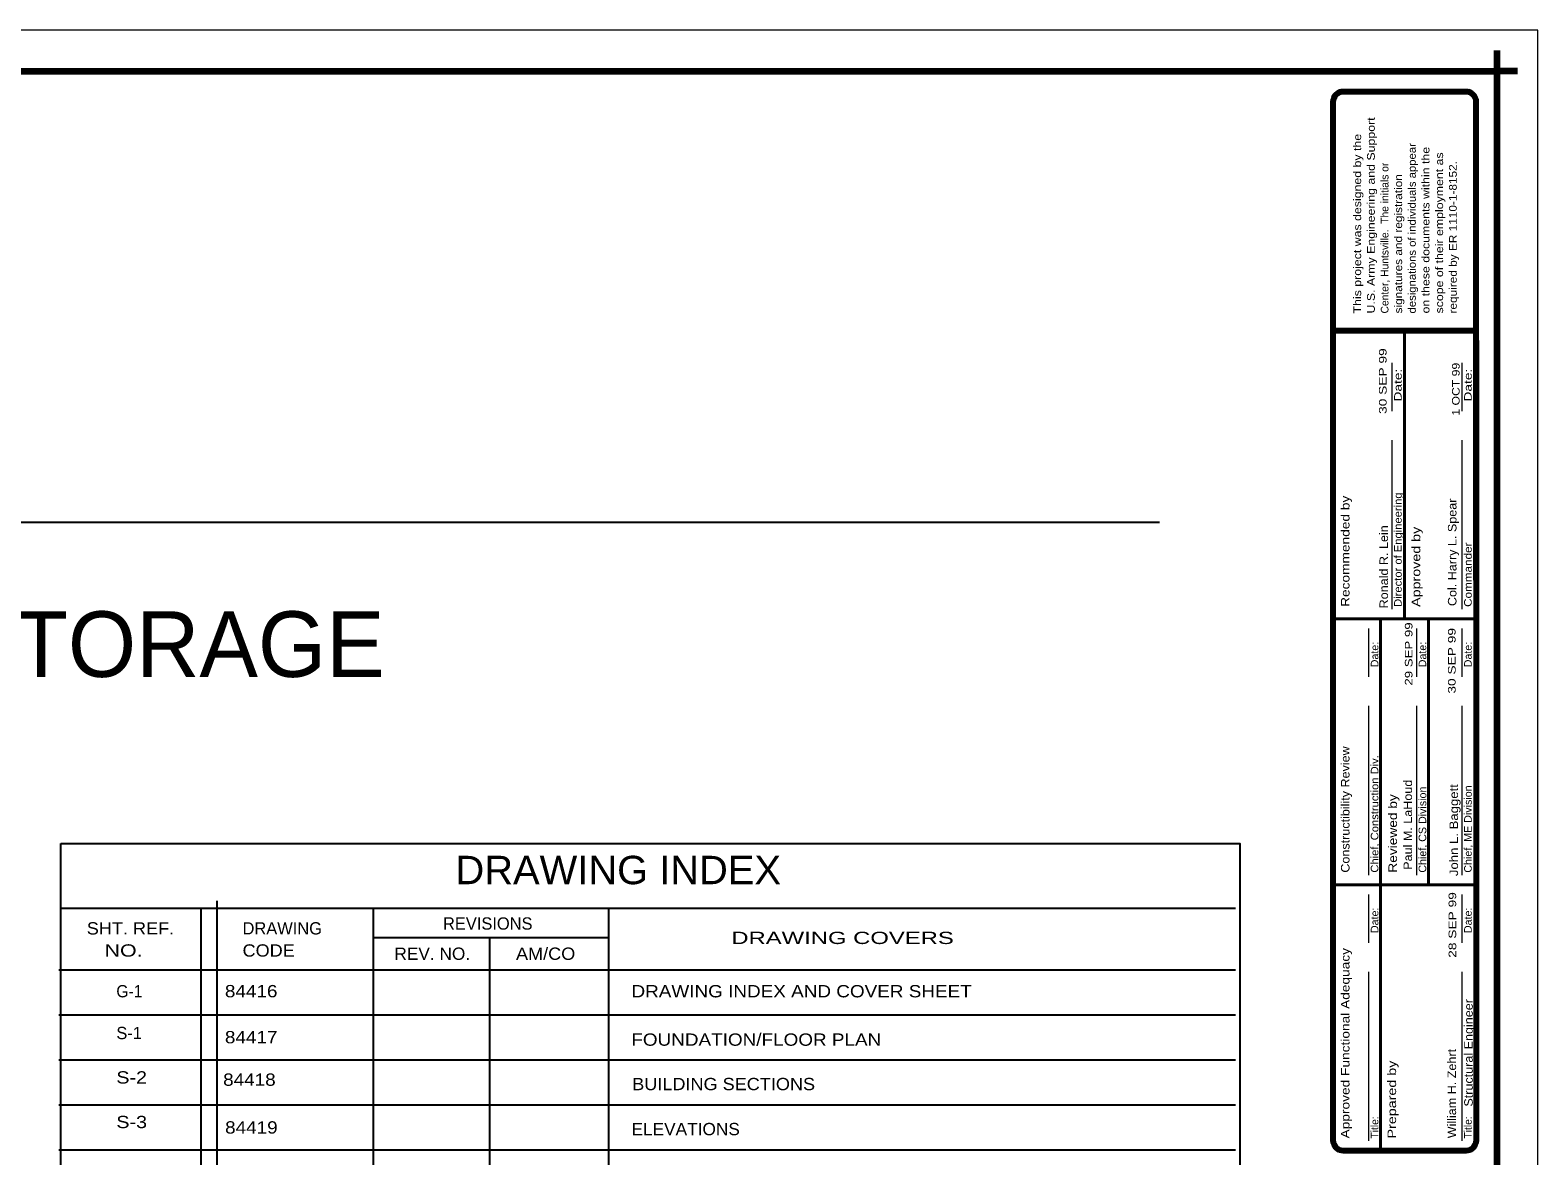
# Model space of a CAD drawing. Extents: x -153.1 to -120, y 360.9 to 384.2.
# Drawn here: x -137.36 to -119.98, y 371.27 to 384.24 of the extents above; entities that cross this region are included whole.
import ezdxf

# ---------------------------------------------------------------- set-up
doc = ezdxf.new("R2010")
doc.units = 0
doc.header["$LTSCALE"] = 0.039
for name, color, linetype, lineweight in [('1', 7, 'Continuous', 80), ('2', 7, 'Continuous', 53), ('3', 7, 'Continuous', 80), ('63', 7, 'Continuous', 25), ('8', 7, 'Continuous', 25)]:
    doc.layers.add(name, color=color, linetype=linetype, lineweight=lineweight)
doc.layers.add('7', color=7, linetype='Continuous')

msp = doc.modelspace()

# ---------------------------------------------------------------- linework, layer by layer
at = {"layer": '1', "lineweight": 90}
for p in [(-120.44775, 384.00407), (-120.44775, 384.00407), (-120.21152, 383.76784), (-120.21152, 383.76784)]:
    msp.add_line(p, (-120.44775, 383.76784), dxfattribs=at)
at = {"layer": '1'}
for p, q in [((-120.80306, 383.53003), (-122.22037, 383.53003)), ((-120.80306, 383.53003), (-122.22037, 383.53003)), ((-122.33848, 383.41193), (-122.33848, 377.90222)), ((-122.33848, 383.41193), (-122.33848, 377.90222)), ((-120.68496, 377.90222), (-120.68496, 383.41193)), ((-120.68496, 377.90222), (-120.68496, 383.41193)), ((-120.68496, 380.7762), (-122.33848, 380.7762)), ((-120.68496, 380.7762), (-122.33848, 380.7762)), ((-122.3375, 380.66461), (-122.3375, 371.44557)), ((-122.3375, 380.66461), (-122.3375, 371.44557)), ((-120.68396, 371.44557), (-120.68396, 380.66461)), ((-120.68396, 371.44557), (-120.68396, 380.66461)), ((-122.21937, 371.32747), (-120.80208, 371.32747)), ((-122.21937, 371.32747), (-120.80208, 371.32747))]:
    msp.add_line(p, q, dxfattribs=at)
at = {"layer": '1', "lineweight": 13}
for p, q in [((-121.65856, 380.40559), (-121.65856, 379.84864)), ((-121.65856, 380.40559), (-121.65856, 379.84864)), ((-120.85104, 380.40559), (-120.85104, 379.84864)), ((-120.85104, 380.40559), (-120.85104, 379.84864)), ((-121.65856, 379.51449), (-121.65856, 377.5652)), ((-121.65856, 379.51449), (-121.65856, 377.5652)), ((-120.85104, 379.51449), (-120.85104, 377.5652)), ((-120.85104, 379.51449), (-120.85104, 377.5652)), ((-121.92727, 377.34243), (-121.92727, 376.78551)), ((-121.92727, 377.34243), (-121.92727, 376.78551)), ((-121.37519, 377.34243), (-121.37519, 376.78551)), ((-121.37519, 377.34243), (-121.37519, 376.78551)), ((-120.85104, 377.34243), (-120.85104, 376.78551)), ((-120.85104, 377.34243), (-120.85104, 376.78551)), ((-121.92727, 376.4513), (-121.92727, 374.50205)), ((-121.92727, 376.4513), (-121.92727, 374.50205)), ((-121.37519, 376.4513), (-121.37519, 374.50205)), ((-121.37519, 376.4513), (-121.37519, 374.50205)), ((-120.85104, 376.4513), (-120.85104, 374.50205)), ((-120.85104, 376.4513), (-120.85104, 374.50205)), ((-121.92727, 374.27924), (-121.92727, 373.72232)), ((-121.92727, 374.27924), (-121.92727, 373.72232)), ((-120.85104, 374.27924), (-120.85104, 373.72232)), ((-120.85104, 374.27924), (-120.85104, 373.72232)), ((-121.92727, 373.38814), (-121.92727, 371.43889)), ((-121.92727, 373.38814), (-121.92727, 371.43889)), ((-120.85104, 373.38814), (-120.85104, 371.43889)), ((-120.85104, 373.38814), (-120.85104, 371.43889))]:
    msp.add_line(p, q, dxfattribs=at)
at = {"layer": '1', "lineweight": 25}
for p in [(-124.33602, 378.5668), (-126.54058, 378.5668)]:
    msp.add_line(p, (-149.54265, 378.5668), dxfattribs=at)
at = {"layer": '1', "lineweight": 13}
msp.add_lwpolyline([(-153.08523, 360.85466), (-119.97531, 360.85466), (-119.97531, 384.24028), (-153.08523, 384.24028)], close=True, dxfattribs=at)
msp.add_lwpolyline([(-153.08523, 360.85466), (-119.97531, 360.85466), (-119.97531, 384.24028), (-153.08523, 384.24028)], close=True, dxfattribs=at)
msp.add_lwpolyline([(-153.08523, 360.85466), (-119.97531, 360.85466), (-119.97531, 384.24028), (-153.08523, 384.24028)], close=True, dxfattribs=at)
at = {"layer": '1', "lineweight": 90}
msp.add_lwpolyline([(-152.02225, 383.76784), (-120.44775, 383.76784), (-120.44775, 361.32709)], dxfattribs=at)
msp.add_lwpolyline([(-152.02225, 383.76784), (-120.44775, 383.76784), (-120.44775, 361.32709)], dxfattribs=at)
msp.add_lwpolyline([(-152.02225, 383.76784), (-120.44775, 383.76784), (-120.44775, 361.32709)], dxfattribs=at)
at = {"layer": '1'}
for centre, start, end in [((-122.21937, 371.44558), 180, 270), ((-122.21937, 371.44558), 180, 270), ((-120.80206, 371.44558), 270, 0), ((-120.80206, 371.44558), 270, 0)]:
    msp.add_arc(centre, 0.11811, start, end, dxfattribs=at)
at = {"layer": '2', "lineweight": 40}
for p, q in [((-121.51073, 380.7762), (-121.51073, 377.4538)), ((-121.51073, 380.7762), (-121.51073, 377.4538)), ((-120.68396, 377.4538), (-122.3375, 377.4538)), ((-120.68396, 377.4538), (-122.3375, 377.4538)), ((-121.788, 377.4538), (-121.788, 371.32747)), ((-121.788, 377.4538), (-121.788, 371.32747)), ((-121.236, 377.4538), (-121.236, 374.39064)), ((-121.236, 377.4538), (-121.236, 374.39064)), ((-120.68396, 374.39064), (-122.3375, 374.39064)), ((-120.68396, 374.39064), (-122.3375, 374.39064))]:
    msp.add_line(p, q, dxfattribs=at)
at = {"layer": '3'}
for centre, start, end in [((-122.22037, 383.41191), 90, 180), ((-122.22037, 383.41191), 90, 180), ((-120.80306, 383.41191), 0, 90), ((-120.80306, 383.41191), 0, 90)]:
    msp.add_arc(centre, 0.11811, start, end, dxfattribs=at)
at = {"layer": '63'}
msp.add_lwpolyline([(-137.00331, 374.8668), (-123.41131, 374.8668), (-123.41131, 361.87971), (-137.00331, 361.87971)], close=True, dxfattribs=at)
at = {"layer": '8'}
for p, q in [((-137.01536, 374.12059), (-123.46037, 374.12059)), ((-135.38806, 374.12059), (-135.38806, 361.89876)), ((-135.20612, 374.20461), (-135.20612, 361.90815)), ((-133.40354, 374.12059), (-133.40354, 361.91753)), ((-130.68806, 374.12059), (-130.68806, 361.90815)), ((-133.40354, 373.78197), (-130.68806, 373.78197)), ((-132.06006, 373.78197), (-132.06006, 361.89876)), ((-137.02615, 373.40903), (-123.46037, 373.40903)), ((-137.02615, 372.89101), (-123.46037, 372.89101)), ((-137.02615, 372.37299), (-123.46037, 372.37299)), ((-137.02615, 371.85497), (-123.46037, 371.85497)), ((-137.02615, 371.33697), (-123.46037, 371.33697))]:
    msp.add_line(p, q, dxfattribs=at)

# ---------------------------------------------------------------- texts
at = {"layer": '1'}
for s, width, p in [('U.S. Army Engineering and Support ', 1.2, (-121.85496, 380.97505)), ('U.S. Army Engineering and Support ', 1.2, (-121.85496, 380.97505)), ('This project was designed by the ', 1.2, (-122.01244, 380.97501)), ('This project was designed by the ', 1.2, (-122.01244, 380.97501)), ('designations of individuals appear', 1.1, (-121.38254, 380.97505)), ('designations of individuals appear', 1.1, (-121.38254, 380.97505)), ('on these documents within the ', 1.2, (-121.22504, 380.97505)), ('on these documents within the ', 1.2, (-121.22504, 380.97505)), ('scope of their employment as ', 1.2, (-121.06756, 380.97505)), ('scope of their employment as ', 1.2, (-121.06756, 380.97505)), ('required by ER 1110-1-8152.', 1.15, (-120.9101, 380.97505)), ('required by ER 1110-1-8152.', 1.15, (-120.9101, 380.97505)), ('signatures and registration ', 1.15, (-121.54, 380.97505)), ('signatures and registration ', 1.15, (-121.54, 380.97505))]:
    msp.add_text(s, height=0.08858, rotation=90, dxfattribs=dict(at, width=width)).set_placement(p)
msp.add_text('Center, Huntsville.  The initials or ', height=0.08858, rotation=90, dxfattribs=at).set_placement((-121.69748, 380.97505))
msp.add_text('Center, Huntsville.  The initials or ', height=0.08858, rotation=90, dxfattribs=at).set_placement((-121.69748, 380.97505))
msp.add_text('AIR FORCE MODULAR STORAGE', height=0.7559, dxfattribs=at).set_placement((-149.33323, 376.78586))
at = {"layer": '2'}
for s, height, width, p in [('30 SEP 99', 0.08768, 1.35, (-121.71905, 379.81704)), ('Date:', 0.08771, 1.35, (-121.54529, 379.96001)), ('Date:', 0.08771, 1.35, (-121.54529, 379.96001)), ('1 OCT 99', 0.08768, 1.2, (-120.87694, 379.79715)), ('Date:', 0.08771, 1.35, (-120.73769, 379.96001)), ('Date:', 0.08771, 1.35, (-120.73769, 379.96001)), ('Recommended by', 0.09842, 1.2, (-122.14675, 377.59303)), ('Recommended by', 0.09842, 1.2, (-122.14675, 377.59303)), ('Director of Engineering', 0.08768, 1.1, (-121.54529, 377.59303)), ('Director of Engineering', 0.08768, 1.1, (-121.54529, 377.59303)), ('Approved by', 0.09842, 1.25, (-121.33106, 377.59303)), ('Approved by', 0.09842, 1.25, (-121.33106, 377.59303)), ('Commander', 0.08768, 1.15, (-120.73769, 377.59303)), ('Commander', 0.08768, 1.15, (-120.73769, 377.59303)), ('29 SEP 99', 0.08768, 1.3, (-121.42066, 376.68607)), ('30 SEP 99', 0.08768, 1.35, (-120.92335, 376.59321)), ('Date:', 0.08768, 1.05, (-121.81392, 376.89689)), ('Date:', 0.08768, 1.05, (-121.81392, 376.89689)), ('Date:', 0.08768, 1.05, (-121.26187, 376.89689)), ('Date:', 0.08768, 1.05, (-121.26187, 376.89689)), ('Date:', 0.08768, 1.05, (-120.73769, 376.89689)), ('Date:', 0.08768, 1.05, (-120.73769, 376.89689)), ('Constructibility Review', 0.09842, 1.1, (-122.14675, 374.52986)), ('Constructibility Review', 0.09842, 1.1, (-122.14675, 374.52986)), ('Chief, Construction Div.', 0.08768, 1.1, (-121.81392, 374.52986)), ('Chief, Construction Div.', 0.08768, 1.1, (-121.81392, 374.52986)), ('Paul M. LaHoud', 0.09843, 1.1, (-121.42566, 374.56304)), ('Chief, CS Division', 0.08768, 1.05, (-121.26187, 374.52986)), ('Chief, CS Division', 0.08768, 1.05, (-121.26187, 374.52986)), ('John L. Baggett', 0.09843, 1.15, (-120.89519, 374.49006)), ('Chief, ME Division', 0.08768, 1.05, (-120.73769, 374.52986)), ('Chief, ME Division', 0.08768, 1.05, (-120.73769, 374.52986)), ('Reviewed by', 0.09842, 1.2, (-121.59969, 374.52986)), ('Reviewed by', 0.09842, 1.2, (-121.59969, 374.52986)), ('28 SEP 99', 0.08768, 1.35, (-120.91672, 373.54848)), ('Date:', 0.08768, 1.05, (-121.81392, 373.83372)), ('Date:', 0.08768, 1.05, (-121.81392, 373.83372)), ('Date:', 0.08768, 1.05, (-120.73769, 373.83372)), ('Date:', 0.08768, 1.05, (-120.73769, 373.83372)), ('Approved Functional Adequacy', 0.09842, 1.2, (-122.14675, 371.46674)), ('Approved Functional Adequacy', 0.09842, 1.2, (-122.14675, 371.46674)), ('Prepared by', 0.09842, 1.25, (-121.60952, 371.46674)), ('Prepared by', 0.09842, 1.25, (-121.60952, 371.46674))]:
    msp.add_text(s, height=height, rotation=90, dxfattribs=dict(at, width=width)).set_placement(p)
for p in [(-121.81392, 371.46674), (-121.81392, 371.46674), (-120.73769, 371.46674), (-120.73769, 371.46674)]:
    msp.add_text('Title:', height=0.08768, rotation=90, dxfattribs=at).set_placement(p)
at = {"layer": '3', "width": 1.1}
for s, height, p in [('Col. Harry L. Spear', 0.09843, (-120.91344, 377.60252)), ('Ronald R. Lein', 0.09843, (-121.7025, 377.57599)), ('Structural Engineer', 0.09842, (-120.72575, 371.83353)), ('William H. Zehrt', 0.09843, (-120.91804, 371.4687))]:
    msp.add_text(s, height=height, rotation=90, dxfattribs=at).set_placement(p)
at = {"layer": '7'}
for s, height, width, p in [('DRAWING INDEX', 0.3273, 1.05, (-132.45387, 374.39701)), ('SHT. REF.', 0.1417, 1.1, (-136.70462, 373.81722)), ('                    DRAWING COVERS', 0.1417, 1.45, (-130.8001, 373.70743)), ('   NO.', 0.1417, 1.3, (-136.70462, 373.56228)), ('CODE ', 0.1417, 1.1, (-134.90854, 373.56228)), ('REV. NO.', 0.1417, 1.05, (-133.15808, 373.52499)), ('AM/CO', 0.1417, 1.1, (-131.75604, 373.52499)), ('G-1', 0.1417, 0.95, (-136.36356, 373.09274)), ('84416', 0.1417, 1.15, (-135.11194, 373.09336)), ('DRAWING INDEX AND COVER SHEET', 0.1417, 1.15, (-130.42437, 373.09274)), ('84417', 0.1417, 1.15, (-135.11194, 372.56303)), ('FOUNDATION/FLOOR PLAN', 0.1417, 1.15, (-130.42653, 372.53493)), ('S-2', 0.1417, 1.2, (-136.36356, 372.09924)), ('84418', 0.1417, 1.15, (-135.13233, 372.07349)), ('BUILDING SECTIONS', 0.1417, 1.1, (-130.41621, 372.02276)), ('S-3', 0.1417, 1.2, (-136.36356, 371.58545)), ('84419', 0.1417, 1.15, (-135.10967, 371.52274)), ('ELEVATIONS', 0.1417, 1.05, (-130.42465, 371.50386))]:
    msp.add_text(s, height=height, dxfattribs=dict(at, width=width)).set_placement(p)
for s, p in [('DRAWING', (-134.90854, 373.81722)), ('REVISIONS', (-132.59754, 373.87316)), ('S-1', (-136.36356, 372.61099))]:
    msp.add_text(s, height=0.1417, dxfattribs=at).set_placement(p)

doc.saveas('drawing.dxf')
